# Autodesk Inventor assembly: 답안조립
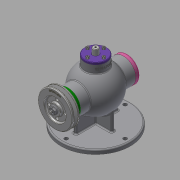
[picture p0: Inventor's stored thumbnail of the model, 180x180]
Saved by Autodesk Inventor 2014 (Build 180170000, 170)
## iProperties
Created: 2020-08
Part Number: 답안조립
Document SubType Name: Assembly
Designer: kh
Author: kh
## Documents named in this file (18)
- C:\Users\kh\Desktop\700806V1025\답안조립.iam
- C:\Users\kh\Desktop\700806V1025\본체.ipt
- C:\Users\kh\Desktop\700806V1025\V-벨트풀리.ipt
- C:\Users\kh\Desktop\700806V1025\너트 M8.ipt
- C:\Users\kh\Desktop\700806V1025\뒤커버.ipt
- C:\Users\kh\Desktop\700806V1025\멈춤링 15x1.ipt
- C:\Users\kh\Desktop\700806V1025\멈춤링 35x1.6.ipt
- 멈춤링 35x1.6.ipt
- C:\Users\kh\Desktop\700806V1025\베어링 6202.ipt
- 베어링 6202.ipt
- C:\Users\kh\Desktop\700806V1025\볼트 M4.ipt
- C:\Users\kh\Desktop\700806V1025\상부커버.ipt
- C:\Users\kh\Desktop\700806V1025\슬라이드.ipt
- C:\Users\kh\Desktop\700806V1025\앞커버.ipt
- C:\Users\kh\Desktop\700806V1025\오일 실 15 30 7.ipt
- C:\Users\kh\Desktop\700806V1025\칼라.ipt
- C:\Users\kh\Desktop\700806V1025\키 3x3x12.ipt
- C:\Users\kh\Desktop\700806V1025\편심축.ipt
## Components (1 placed, 1 different names)
1. V-벨트풀리:1 — Insert:16, Mate:6, Insert:17
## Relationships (3: Insert 2, Mate 1)
- Insert:16: V-벨트풀리:1
- Mate:6: V-벨트풀리:1
- Insert:17: V-벨트풀리:1
